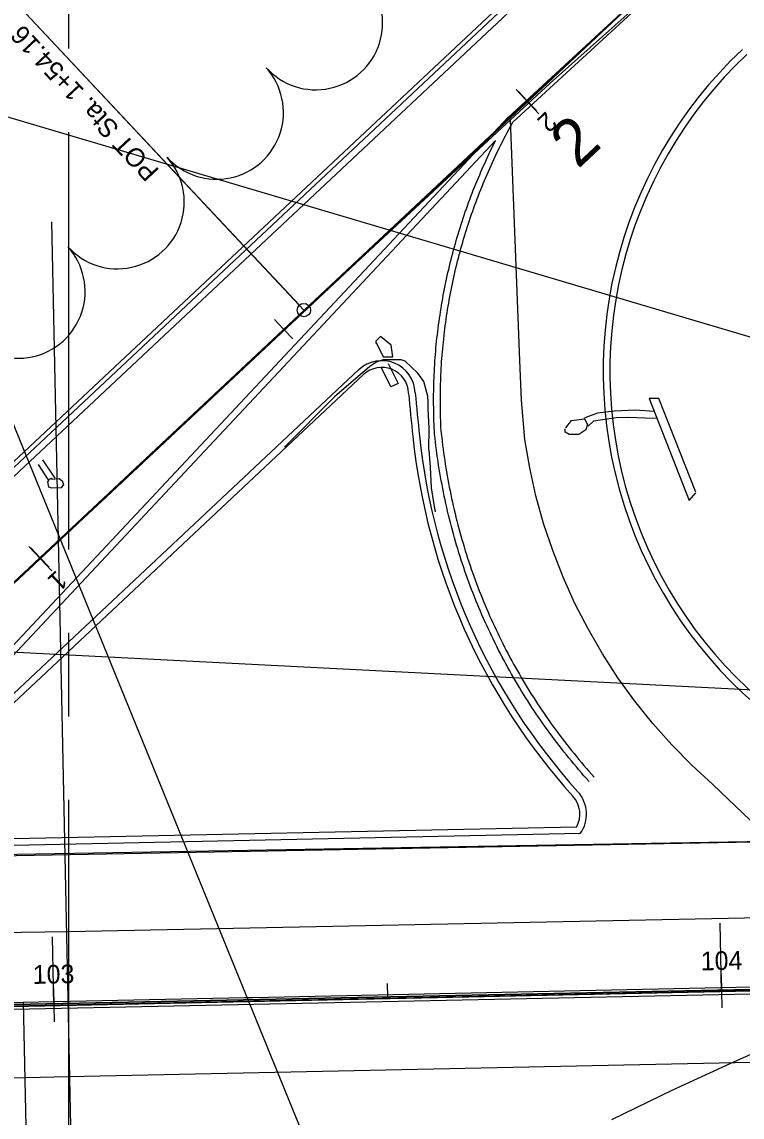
# Model space of a CAD drawing. Extents: x -25029 to 2274964, y -81170 to 687028.
# Drawn here: x -4299.6 to -4191.7, y -66441.4 to -66277.4 of the extents above; entities that cross this region are included whole.
import ezdxf

# ---------------------------------------------------------------- set-up
doc = ezdxf.new("R2010")
doc.units = 0
for name, color, linetype in [('81911BEA - RW_X_Fee_RW', 7, 'Continuous'), ('AP_X_Runway', 7, 'Continuous'), ('BD_X_Canopy', 7, 'Continuous'), ('Default', 7, 'Continuous'), ('DIVISIONS', 7, 'Continuous'), ('GE_X_CL_100', 7, 'Continuous'), ('GE_X_CL_20', 7, 'Continuous'), ('GK_Visualization', 7, 'Continuous'), ('MT_P_Lane_Line', 7, 'Continuous'), ('PM_P_CL_Double_Solid', 7, 'Continuous'), ('PM_P_Stop_Line', 7, 'Continuous'), ('PV_X_Curb', 7, 'Continuous'), ('PV_X_EOP', 7, 'Continuous'), ('RD_P_Gate', 7, 'Continuous'), ('RD_X_GR_Rt', 7, 'Continuous'), ('TREES', 7, 'Continuous')]:
    doc.layers.add(name, color=color, linetype=linetype)

msp = doc.modelspace()

# ---------------------------------------------------------------- linework, layer by layer
at = {"layer": '81911BEA - RW_X_Fee_RW'}
msp.add_line((-4315.27, -66287.59), (-4039.77, -66369.33), dxfattribs=at)
at = {"layer": 'AP_X_Runway'}
for p, q in [((-4045.24, -66105.82), (-4335.98, -66378.47)), ((-3993.27, -66387.51), (-4428.93, -66365.26)), ((-4384.25, -66403.48), (-4101.06, -66398.53)), ((-4292.61, -66400.74), (-4292.61, -66446.91)), ((-3221.39, -66402.05), (-5080.45, -66441.35))]:
    msp.add_line(p, q, dxfattribs=at)
msp.add_arc((-4146.54, -66329.69), 66, 133.1608, 266.3388, dxfattribs=at)
at = {"layer": 'BD_X_Canopy'}
for p, q in [((-4369.84, -66425.97), (-3988.3, -66068.47)), ((-4257.35, -66320.56), (-4393.33, -66175.43)), ((-3994.85, -66418.3), (-4628.49, -66431.16))]:
    msp.add_line(p, q, dxfattribs=at)
at = {"layer": 'Default'}
for p, q in [((-4406.23, -66460.38), (-3988.37, -66068.52)), ((-3988.37, -66068.52), (-4369.76, -66426.18)), ((-4225.59, -66287.55), (-4222.17, -66291.2)), ((-4223.88, -66289.37), (-4223.88, -66289.37)), ((-4298.53, -66355.95), (-4295.11, -66359.6)), ((-4296.82, -66357.78), (-4296.82, -66357.78)), ((-4819.56, -66435.63), (-2645.14, -66389.94)), ((-4644.7, -66431.96), (-2645.14, -66389.94)), ((-4819.55, -66436.13), (-4021.18, -66419.36)), ((-4194.85, -66420.01), (-4194.75, -66425)), ((-4294.83, -66422.11), (-4294.73, -66427.11)), ((-4194.8, -66422.51), (-4194.8, -66422.51)), ((-4194.8, -66422.51), (-4194.8, -66422.51)), ((-4194.8, -66422.51), (-4194.8, -66422.51)), ((-4294.78, -66424.61), (-4294.78, -66424.61))]:
    msp.add_line(p, q, dxfattribs=at)
for points in [[(-4220.23, -66285.95), (-4187.4, -66255.17)], [(-4225.7, -66291.08), (-4222.05, -66287.66)], [(-4260.35, -66323.57), (-4227.52, -66292.79)], [(-4293.17, -66354.36), (-4260.35, -66323.57)], [(-4298.64, -66359.49), (-4295, -66356.07)], [(-4244.79, -66423.56), (-4199.8, -66422.61)], [(-4197.3, -66422.56), (-4192.3, -66422.45)], [(-4297.28, -66424.66), (-4292.28, -66424.55)], [(-4289.78, -66424.5), (-4244.79, -66423.56)]]:
    msp.add_lwpolyline(points, dxfattribs=at)
msp.add_arc((-3934.03, -66305.4), 307.89, 185.1321, 186.3401, dxfattribs=at)
at = {"layer": 'DIVISIONS'}
for p, q in [((-4292.61, -66268.9), (-4292.61, -66281.4)), ((-4292.61, -66293.9), (-4292.61, -66356.4)), ((-4304.96, -66327.66), (-4245.68, -66472.98)), ((-4292.61, -66368.9), (-4292.61, -66381.4)), ((-4292.61, -66393.9), (-4292.61, -66406.4)), ((-4292.61, -66418.9), (-4292.61, -66424.04)), ((-4292.61, -66424.04), (-4292.61, -66481.4))]:
    msp.add_line(p, q, dxfattribs=at)
at = {"layer": 'GE_X_CL_100'}
for p, q in [((-4194.8, -66422.36), (-4195.01, -66412.36)), ((-4294.78, -66424.39), (-4294.99, -66414.39))]:
    msp.add_line(p, q, dxfattribs=at)
for points in [[(-4088.16, -66164.72), (-4110.37, -66185.78), (-4151.55, -66223.69), (-4186.81, -66256.55), (-4220.49, -66286.59), (-4226.43, -66292.08)], [(-4226.43, -66292.08), (-4248.83, -66312.82), (-4286.92, -66348.54), (-4293.71, -66354.8)], [(-4164.81, -66421.49), (-4196.1, -66391.6), (-4199.26, -66388.7), (-4202.27, -66385.64), (-4205.12, -66382.44), (-4207.81, -66379.09), (-4210.32, -66375.61), (-4212.66, -66372.01), (-4214.8, -66368.3), (-4216.76, -66364.48), (-4218.53, -66360.57), (-4220.09, -66356.57), (-4221.45, -66352.49), (-4222.6, -66348.36), (-4223.54, -66344.17), (-4224.26, -66339.94), (-4224.75, -66334.03), (-4225.03, -66328.1), (-4226.43, -66292.08)], [(-4293.71, -66354.8), (-4325.64, -66384.25), (-4372.87, -66425.67)], [(-4265, -66423.46), (-4183.31, -66421.75), (-4164.81, -66421.49)], [(-4372.87, -66425.67), (-4365.75, -66425.56), (-4266.24, -66423.49), (-4265, -66423.46)], [(-4183.64, -66429.03), (-4192.94, -66433.09), (-4202.15, -66437.35), (-4211.28, -66441.8)]]:
    msp.add_lwpolyline(points, dxfattribs=at)
at = {"layer": 'GE_X_CL_20'}
for p, q in [((-4258.03, -66319.83), (-4303.01, -66271.83)), ((-4223.9, -66289.22), (-4225.26, -66287.76)), ((-4223.9, -66289.22), (-4222.53, -66290.68)), ((-4260.38, -66323.41), (-4261.75, -66321.95)), ((-4260.38, -66323.41), (-4259.02, -66324.87)), ((-4296.87, -66357.6), (-4298.24, -66356.14)), ((-4296.87, -66357.6), (-4295.5, -66359.05)), ((-4194.8, -66422.36), (-4194.85, -66420.36)), ((-4294.78, -66424.39), (-4294.82, -66422.39)), ((-4244.79, -66423.38), (-4244.83, -66421.38))]:
    msp.add_line(p, q, dxfattribs=at)
msp.add_circle((-4257.35, -66320.56), 1, dxfattribs=at)
at = {"layer": 'GK_Visualization'}
for p, q in [((-4257.41, -66320.63), (-4257.28, -66320.5)), ((-4257.41, -66320.5), (-4257.28, -66320.63)), ((-4371.16, -66425.94), (-3994.85, -66418.3))]:
    msp.add_line(p, q, dxfattribs=at)
at = {"layer": 'MT_P_Lane_Line'}
for p, q in [((-4676.25, -66418.62), (-4292.61, -66413.59)), ((-4292.61, -66435.3), (-4094.6, -66431.14)), ((-4640.98, -66444), (-4292.61, -66435.3))]:
    msp.add_line(p, q, dxfattribs=at)
msp.add_lwpolyline([(-4292.61, -66413.59), (-4095.04, -66409.59)], dxfattribs=at)
at = {"layer": 'PM_P_CL_Double_Solid'}
for p, q in [((-4226.77, -66291.71), (-4081.98, -66158.18)), ((-4226.07, -66292.43), (-4081.31, -66158.91)), ((-4324.01, -66395.44), (-4226.75, -66291.69)), ((-4323.03, -66395.86), (-4228.66, -66295.19)), ((-4292.61, -66424.35), (-3994.85, -66418.3)), ((-4371.16, -66425.94), (-4292.61, -66424.35))]:
    msp.add_line(p, q, dxfattribs=at)
for points in [[(-4236.77, -66339.08), (-4236.8, -66338.59), (-4236.83, -66338.1), (-4236.85, -66337.61), (-4236.87, -66337.12), (-4236.88, -66336.63), (-4236.9, -66336.14), (-4236.91, -66335.64), (-4236.91, -66335.15), (-4236.92, -66334.66), (-4236.92, -66334.17), (-4236.92, -66333.68), (-4236.92, -66333.19), (-4236.91, -66332.7), (-4236.9, -66332.21), (-4236.89, -66331.71), (-4236.87, -66331.22), (-4236.86, -66330.73), (-4236.84, -66330.24), (-4236.81, -66329.75), (-4236.79, -66329.26), (-4236.76, -66328.77), (-4236.73, -66328.28), (-4236.69, -66327.79), (-4236.65, -66327.3), (-4236.61, -66326.81), (-4236.57, -66326.32), (-4236.52, -66325.83), (-4236.47, -66325.34), (-4236.42, -66324.85), (-4236.37, -66324.37), (-4236.31, -66323.88), (-4236.25, -66323.39), (-4236.19, -66322.9), (-4236.12, -66322.42), (-4236.05, -66321.93), (-4235.98, -66321.44), (-4235.91, -66320.96), (-4235.83, -66320.47), (-4235.75, -66319.99), (-4235.67, -66319.5), (-4235.58, -66319.02), (-4235.5, -66318.54), (-4235.4, -66318.05), (-4235.31, -66317.57), (-4235.21, -66317.09), (-4235.11, -66316.61), (-4235.01, -66316.13), (-4234.91, -66315.65), (-4234.8, -66315.17), (-4234.69, -66314.69), (-4234.58, -66314.21), (-4234.46, -66313.73), (-4234.34, -66313.26), (-4234.22, -66312.78), (-4234.1, -66312.31), (-4233.97, -66311.83), (-4233.84, -66311.36), (-4233.71, -66310.88), (-4233.57, -66310.41), (-4233.43, -66309.94), (-4233.29, -66309.47), (-4233.15, -66309), (-4233.01, -66308.53), (-4232.86, -66308.06), (-4232.71, -66307.59), (-4232.55, -66307.13), (-4232.39, -66306.66), (-4232.23, -66306.2), (-4232.07, -66305.73), (-4231.91, -66305.27), (-4231.74, -66304.81), (-4231.57, -66304.35), (-4231.4, -66303.89), (-4231.22, -66303.43), (-4231.04, -66302.97), (-4230.86, -66302.51), (-4230.68, -66302.06), (-4230.49, -66301.6), (-4230.31, -66301.15), (-4230.11, -66300.7), (-4229.92, -66300.25), (-4229.72, -66299.8), (-4229.53, -66299.35), (-4229.32, -66298.9), (-4229.12, -66298.45), (-4228.91, -66298.01), (-4228.7, -66297.56), (-4228.49, -66297.12), (-4228.28, -66296.68), (-4228.06, -66296.24), (-4227.84, -66295.8), (-4227.62, -66295.36), (-4227.39, -66294.92), (-4227.17, -66294.49), (-4226.94, -66294.05), (-4226.07, -66292.43)], [(-4237.77, -66339.14), (-4237.8, -66338.64), (-4237.82, -66338.15), (-4237.85, -66337.65), (-4237.87, -66337.15), (-4237.88, -66336.66), (-4237.9, -66336.16), (-4237.91, -66335.66), (-4237.91, -66335.17), (-4237.92, -66334.67), (-4237.92, -66334.17), (-4237.92, -66333.68), (-4237.92, -66333.18), (-4237.91, -66332.68), (-4237.9, -66332.18), (-4237.89, -66331.69), (-4237.87, -66331.19), (-4237.86, -66330.69), (-4237.84, -66330.2), (-4237.81, -66329.7), (-4237.79, -66329.2), (-4237.76, -66328.71), (-4237.72, -66328.21), (-4237.69, -66327.72), (-4237.65, -66327.22), (-4237.61, -66326.72), (-4237.57, -66326.23), (-4237.52, -66325.73), (-4237.47, -66325.24), (-4237.42, -66324.75), (-4237.36, -66324.25), (-4237.3, -66323.76), (-4237.24, -66323.26), (-4237.18, -66322.77), (-4237.11, -66322.28), (-4237.04, -66321.79), (-4236.97, -66321.3), (-4236.9, -66320.8), (-4236.82, -66320.31), (-4236.74, -66319.82), (-4236.65, -66319.33), (-4236.57, -66318.84), (-4236.48, -66318.35), (-4236.39, -66317.87), (-4236.29, -66317.38), (-4236.19, -66316.89), (-4236.09, -66316.4), (-4235.99, -66315.92), (-4235.88, -66315.43), (-4235.78, -66314.95), (-4235.66, -66314.46), (-4235.55, -66313.98), (-4235.43, -66313.5), (-4235.31, -66313.01), (-4235.19, -66312.53), (-4235.06, -66312.05), (-4234.94, -66311.57), (-4234.8, -66311.09), (-4234.67, -66310.61), (-4234.53, -66310.13), (-4234.39, -66309.66), (-4234.25, -66309.18), (-4234.11, -66308.71), (-4233.96, -66308.23), (-4233.81, -66307.76), (-4233.66, -66307.28), (-4233.5, -66306.81), (-4233.34, -66306.34), (-4233.18, -66305.87), (-4233.02, -66305.4), (-4232.85, -66304.93), (-4232.68, -66304.47), (-4232.51, -66304), (-4232.33, -66303.53), (-4232.16, -66303.07), (-4231.98, -66302.61), (-4231.79, -66302.14), (-4231.61, -66301.68), (-4231.42, -66301.22), (-4231.23, -66300.76), (-4231.03, -66300.31), (-4230.84, -66299.85), (-4230.64, -66299.39), (-4230.44, -66298.94), (-4230.23, -66298.49), (-4230.03, -66298.03), (-4229.82, -66297.58), (-4229.61, -66297.13), (-4229.39, -66296.68), (-4229.18, -66296.24), (-4228.66, -66295.19)], [(-4214.63, -66391.14), (-4215.02, -66390.71), (-4215.41, -66390.27), (-4215.79, -66389.83), (-4216.18, -66389.39), (-4216.55, -66388.94), (-4216.93, -66388.49), (-4217.3, -66388.04), (-4217.67, -66387.59), (-4218.04, -66387.14), (-4218.41, -66386.68), (-4218.77, -66386.22), (-4219.13, -66385.76), (-4219.48, -66385.3), (-4219.83, -66384.83), (-4220.18, -66384.36), (-4220.53, -66383.89), (-4220.88, -66383.42), (-4221.22, -66382.95), (-4221.55, -66382.47), (-4221.89, -66381.99), (-4222.22, -66381.51), (-4222.55, -66381.03), (-4222.87, -66380.54), (-4223.2, -66380.05), (-4223.52, -66379.56), (-4223.83, -66379.07), (-4224.15, -66378.58), (-4224.45, -66378.08), (-4224.76, -66377.59), (-4225.07, -66377.09), (-4225.37, -66376.59), (-4225.66, -66376.08), (-4225.96, -66375.58), (-4226.25, -66375.07), (-4226.53, -66374.56), (-4226.82, -66374.05), (-4227.1, -66373.54), (-4227.38, -66373.02), (-4227.65, -66372.51), (-4227.92, -66371.99), (-4228.19, -66371.47), (-4228.46, -66370.95), (-4228.72, -66370.43), (-4228.97, -66369.9), (-4229.23, -66369.38), (-4229.48, -66368.85), (-4229.73, -66368.32), (-4229.97, -66367.79), (-4230.21, -66367.26), (-4230.45, -66366.72), (-4230.69, -66366.19), (-4230.92, -66365.65), (-4231.14, -66365.11), (-4231.37, -66364.57), (-4231.59, -66364.03), (-4231.81, -66363.49), (-4232.02, -66362.95), (-4232.23, -66362.4), (-4232.44, -66361.85), (-4232.64, -66361.31), (-4232.84, -66360.76), (-4233.03, -66360.21), (-4233.23, -66359.66), (-4233.42, -66359.1), (-4233.6, -66358.55), (-4233.78, -66357.99), (-4233.96, -66357.44), (-4234.14, -66356.88), (-4234.31, -66356.32), (-4234.48, -66355.76), (-4234.64, -66355.2), (-4234.8, -66354.64), (-4234.96, -66354.08), (-4235.11, -66353.51), (-4235.26, -66352.95), (-4235.41, -66352.38), (-4235.55, -66351.81), (-4235.69, -66351.25), (-4235.83, -66350.68), (-4235.96, -66350.11), (-4236.09, -66349.54), (-4236.21, -66348.97), (-4236.33, -66348.4), (-4236.45, -66347.82), (-4236.56, -66347.25), (-4236.67, -66346.68), (-4236.78, -66346.1), (-4236.88, -66345.53), (-4236.98, -66344.95), (-4237.08, -66344.37), (-4237.17, -66343.8), (-4237.26, -66343.22), (-4237.34, -66342.64), (-4237.42, -66342.06), (-4237.5, -66341.48), (-4237.57, -66340.9), (-4237.64, -66340.32), (-4237.71, -66339.74), (-4237.77, -66339.16)], [(-4236.78, -66339.06), (-4236.71, -66339.63), (-4236.65, -66340.21), (-4236.58, -66340.78), (-4236.51, -66341.36), (-4236.43, -66341.93), (-4236.35, -66342.5), (-4236.27, -66343.07), (-4236.18, -66343.64), (-4236.09, -66344.21), (-4236, -66344.78), (-4235.9, -66345.35), (-4235.8, -66345.92), (-4235.69, -66346.49), (-4235.58, -66347.06), (-4235.47, -66347.63), (-4235.35, -66348.19), (-4235.23, -66348.76), (-4235.11, -66349.32), (-4234.98, -66349.89), (-4234.85, -66350.45), (-4234.72, -66351.01), (-4234.58, -66351.57), (-4234.44, -66352.13), (-4234.3, -66352.69), (-4234.15, -66353.25), (-4234, -66353.81), (-4233.84, -66354.37), (-4233.68, -66354.92), (-4233.52, -66355.48), (-4233.35, -66356.03), (-4233.18, -66356.58), (-4233.01, -66357.13), (-4232.83, -66357.68), (-4232.65, -66358.23), (-4232.47, -66358.78), (-4232.28, -66359.33), (-4232.09, -66359.87), (-4231.9, -66360.42), (-4231.7, -66360.96), (-4231.5, -66361.5), (-4231.29, -66362.04), (-4231.09, -66362.58), (-4230.88, -66363.12), (-4230.66, -66363.66), (-4230.44, -66364.19), (-4230.22, -66364.73), (-4230, -66365.26), (-4229.77, -66365.79), (-4229.54, -66366.32), (-4229.3, -66366.85), (-4229.06, -66367.37), (-4228.82, -66367.9), (-4228.58, -66368.42), (-4228.33, -66368.94), (-4228.08, -66369.47), (-4227.82, -66369.98), (-4227.56, -66370.5), (-4227.3, -66371.02), (-4227.04, -66371.53), (-4226.77, -66372.04), (-4226.5, -66372.55), (-4226.22, -66373.06), (-4225.94, -66373.57), (-4225.66, -66374.07), (-4225.38, -66374.58), (-4225.09, -66375.08), (-4224.8, -66375.58), (-4224.51, -66376.07), (-4224.21, -66376.57), (-4223.91, -66377.06), (-4223.61, -66377.56), (-4223.3, -66378.05), (-4222.99, -66378.53), (-4222.68, -66379.02), (-4222.36, -66379.5), (-4222.04, -66379.99), (-4221.72, -66380.47), (-4221.39, -66380.94), (-4221.07, -66381.42), (-4220.74, -66381.89), (-4220.4, -66382.37), (-4220.06, -66382.83), (-4219.72, -66383.3), (-4219.38, -66383.77), (-4219.04, -66384.23), (-4218.69, -66384.69), (-4218.33, -66385.15), (-4217.98, -66385.61), (-4217.62, -66386.06), (-4217.26, -66386.51), (-4216.9, -66386.96), (-4216.53, -66387.41), (-4216.16, -66387.85), (-4215.79, -66388.29), (-4215.42, -66388.73), (-4215.04, -66389.17), (-4214.66, -66389.61), (-4214.28, -66390.04), (-4213.89, -66390.47)]]:
    msp.add_lwpolyline(points, dxfattribs=at)
at = {"layer": 'PM_P_Stop_Line'}
for p, q in [((-4245.86, -66324.5), (-4246.58, -66325.22)), ((-4244.3, -66325.81), (-4245.86, -66324.5)), ((-4246.58, -66325.22), (-4246.58, -66325.55)), ((-4246.52, -66325.42), (-4245.47, -66327.57)), ((-4244.04, -66327.57), (-4244.3, -66325.81)), ((-4245.47, -66327.57), (-4244.04, -66327.57)), ((-4247.49, -66329.01), (-4252.75, -66333.56)), ((-4246.43, -66328.31), (-4247.49, -66329.01)), ((-4245.48, -66328.01), (-4246.43, -66328.31)), ((-4244.32, -66332.03), (-4245.74, -66329.23)), ((-4244.13, -66328.01), (-4245.48, -66328.01)), ((-4244.73, -66328.56), (-4243.21, -66331.53)), ((-4242.77, -66328.01), (-4244.13, -66328.01)), ((-4242.18, -66328.19), (-4242.77, -66328.01)), ((-4241.23, -66329.13), (-4242.18, -66328.19)), ((-4240.29, -66330.02), (-4241.23, -66329.13)), ((-4239.4, -66331.26), (-4240.29, -66330.02)), ((-4243.21, -66331.53), (-4244.32, -66332.03)), ((-4238.81, -66333.44), (-4239.4, -66331.26)), ((-4252.75, -66333.56), (-4260.24, -66341.06)), ((-4238.75, -66334.39), (-4238.81, -66333.44)), ((-4238.75, -66335.39), (-4238.75, -66334.39)), ((-4204.2, -66333.79), (-4205.67, -66333.79)), ((-4205.67, -66333.79), (-4199.65, -66349.09)), ((-4198.65, -66347.84), (-4204.2, -66333.79)), ((-4238.58, -66338.23), (-4238.75, -66335.39)), ((-4213.41, -66335.97), (-4215.12, -66336.62)), ((-4210.87, -66335.68), (-4213.41, -66335.97)), ((-4207.74, -66335.56), (-4210.87, -66335.68)), ((-4204.91, -66335.74), (-4207.74, -66335.56)), ((-4218.14, -66338.2), (-4217.3, -66337.1)), ((-4217.3, -66337.1), (-4215.34, -66336.83)), ((-4215.12, -66336.62), (-4215.41, -66336.8)), ((-4215.34, -66336.83), (-4214.88, -66337.68)), ((-4214.88, -66337.68), (-4215.14, -66338.47)), ((-4214, -66337.21), (-4214.76, -66337.92)), ((-4212.64, -66336.98), (-4214, -66337.21)), ((-4210.57, -66336.68), (-4212.64, -66336.98)), ((-4208.8, -66336.62), (-4210.57, -66336.68)), ((-4206.32, -66336.74), (-4208.8, -66336.62)), ((-4204.55, -66336.8), (-4206.32, -66336.74)), ((-4238.64, -66341.48), (-4238.58, -66338.23)), ((-4218.21, -66338.86), (-4218.21, -66338.33)), ((-4217.62, -66339.18), (-4218.21, -66338.86)), ((-4216.19, -66339.18), (-4217.62, -66339.18)), ((-4215.14, -66338.47), (-4216.19, -66339.18)), ((-4238.64, -66341.48), (-4238.46, -66344.08)), ((-4295.62, -66345.91), (-4297.07, -66343.69)), ((-4294.58, -66345.71), (-4296.43, -66342.98)), ((-4238.46, -66344.08), (-4238.28, -66347.15)), ((-4295.69, -66346.28), (-4295.45, -66345.88)), ((-4295.45, -66345.88), (-4295.15, -66345.71)), ((-4295.15, -66345.71), (-4295.05, -66345.81)), ((-4295.15, -66345.85), (-4294, -66345.78)), ((-4294, -66345.78), (-4293.56, -66346.12)), ((-4295.52, -66347.06), (-4295.69, -66346.28)), ((-4295.08, -66347.23), (-4295.52, -66347.06)), ((-4293.7, -66347.16), (-4295.08, -66347.23)), ((-4293.36, -66346.69), (-4293.7, -66347.16)), ((-4293.56, -66346.12), (-4293.36, -66346.69)), ((-4238.28, -66347.15), (-4237.87, -66349.69)), ((-4199.65, -66349.09), (-4198.65, -66347.9)), ((-4237.87, -66349.69), (-4237.69, -66350.75))]:
    msp.add_line(p, q, dxfattribs=at)
at = {"layer": 'PV_X_Curb'}
for p, q in [((-4045.92, -66105.1), (-4336.66, -66377.74)), ((-4248.42, -66330.21), (-4317.61, -66395.1)), ((-4216.53, -66397.96), (-4318.29, -66400.09))]:
    msp.add_line(p, q, dxfattribs=at)
for centre, radius, start, end in [((-4146.54, -66329.69), 65, 133.1608, 266.3388), ((-4245.68, -66333.13), 4, 2.1827, 133.1608), ((-3934.03, -66305.4), 308.89, 185.1321, 186.3401), ((-4146.54, -66329.69), 95, 185.9269, 222.0654), ((-4220.03, -66396.03), 4, 331.2037, 42.1819)]:
    msp.add_arc(centre, radius, start, end, dxfattribs=at)
at = {"layer": 'PV_X_EOP'}
for p, q in [((-4045.24, -66105.82), (-4335.98, -66378.47)), ((-4249.1, -66329.48), (-4318.3, -66394.37)), ((-4215.97, -66398.94), (-4318.81, -66401.11))]:
    msp.add_line(p, q, dxfattribs=at)
msp.add_lwpolyline([(-4389.36, -66403.85), (-4101.06, -66398.53)], dxfattribs=at)
for centre, radius, start, end in [((-4146.54, -66329.69), 66, 133.1608, 266.3388), ((-4245.68, -66333.13), 5, 2.1827, 133.1608), ((-4146.54, -66329.69), 94, 185.9269, 222.0654), ((-4220.03, -66396.03), 5, 324.3333, 42.1819)]:
    msp.add_arc(centre, radius, start, end, dxfattribs=at)
at = {"layer": 'RD_P_Gate'}
for p, q in [((-4290.25, -66537.88), (-4295.09, -66307.36)), ((-4299.37, -66424.18), (-4298.21, -66479.5))]:
    msp.add_line(p, q, dxfattribs=at)
at = {"layer": 'RD_X_GR_Rt'}
msp.add_line((-4046.35, -66104.64), (-4305.1, -66347.28), dxfattribs=at)
at = {"layer": 'TREES'}
for centre in [(-4255.56, -66277.58), (-4270.41, -66290.98), (-4285.26, -66304.38), (-4300.11, -66317.78)]:
    msp.add_arc(centre, 10, 222.0626, 42.0626, dxfattribs=at)

# ---------------------------------------------------------------- texts
at = {"layer": 'Default'}
msp.add_text('2', height=7, rotation=43.1608, dxfattribs=at).set_placement((-4216.33, -66299.53))
at = {"layer": 'GE_X_CL_20'}
for s, rotation, p in [('POT Sta. 1+54.16', 133.136, (-4278.88, -66299.63)), ('2', 223.136, (-4221.08, -66290.7)), ('1', 223.136, (-4294.39, -66359.39)), ('104', 1.1627, (-4197.91, -66419.42)), ('103', 1.1627, (-4297.93, -66421.45))]:
    msp.add_text(s, height=2.8, rotation=rotation, dxfattribs=at).set_placement(p)
at = {"layer": 'GK_Visualization'}
msp.add_text('139', height=0.14, dxfattribs=at).set_placement((-4257.35, -66320.56))

doc.saveas('drawing.dxf')
